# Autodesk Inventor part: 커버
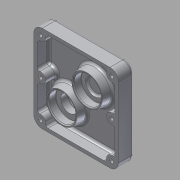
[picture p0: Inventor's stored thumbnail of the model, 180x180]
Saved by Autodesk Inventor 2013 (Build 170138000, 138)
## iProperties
Created: 2015-10
Part Number: 커버
Material: 알루미늄 6061
Document SubType Name: Modeling
Designer: mduedu
Density: 2.71 g/cm^3
Mass: 254.004 g
Surface Area: 401.286 cm^2
Volume: 93.7286 cm^3
Author: mduedu
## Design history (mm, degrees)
sketch "스케치1"
  geometry: L1 (-50, -51.5)-(50, -51.5); L2 (50, -51.5)-(50, 51.5); L3 (50, 51.5)-(-50, 51.5); L4 (-50, 51.5)-(-50, -51.5); L5 (-50, -51.5)-(50, 51.5); L6 (50, -51.5)-(-50, 51.5); 1 further point
  constraints: 12 end point, 2 midpoint, 2 parallel, 1 horizontal, 1 perpendicular
  dimensions: "d0" = 100 distance of L3.end L2.end; "d1" = 103 distance of L2.end L1.end
extrude "돌출1" new body sketch "스케치1" distance "d2" = 18; taper "d3" = 0 deg
fillet "모깎기1" dims "d4" = 10
fillet "모깎기2" dims "d5" = 3
feature "쉘1" dims "d6" = 4
sketch "스케치2"
  geometry: L1 (40, 51.5)-(-40, 51.5) reference; L2 (50, -41.5)-(50, 41.5) reference; L3 (-40, -51.5)-(40, -51.5) reference; L4 (-50, 41.5)-(-50, -41.5) reference; L5 (-50, 0)-(50, 0); L6 (0, 51.5)-(0, -51.5); C1 r 6 at (-42, 43.5); C2 r 6 at (-42, 0); C3 r 6 at (-42, -43.5); C4 r 6 at (42, -43.5); C5 r 6 at (42, 0); C6 r 6 at (42, 43.5); 1 further point
  constraints: 6 centre point, 4 end point, 4 midpoint, 4 symmetric about line, 1 equal radius, 1 point on line, 1 vertical alignment, 4 other
  dimensions: "d7" = 12 diameter of C1; "d8" = 8 distance from line of C1.centre L1; "d9" = 8 distance from line of C1.centre L4
extrude "돌출2" join sketch "스케치2" stored distance "d10" = 0; taper "d11" = 0 deg
fillet "모깎기3" dims "d12" = 3
fillet "모깎기4" dims "d13" = 3
sketch "스케치3"
  geometry: A1 r 6 centre (42, 43.5) between (36.037, 44.167) and (42.667, 37.537) reference; A2 r 6 centre (42, 0) between (42.667, 5.963) and (42.667, -5.963) reference; A3 r 6 centre (42, -43.5) between (42.667, -37.537) and (36.037, -44.167) reference; A4 r 6 centre (-42, -43.5) between (-36.037, -44.167) and (-42.667, -37.537) reference; A5 r 6 centre (-42, 0) between (-42.667, -5.963) and (-42.667, 5.963) reference; A6 r 6 centre (-42, 43.5) between (-42.667, 37.537) and (-36.037, 44.167) reference; 7 further points
  constraints: 6 coincident
hole "구멍1" sketch "스케치3" at (-42, 43.5), (-42, 0), (-42, -43.5), (42, -43.5), (42, 0), (42, 43.5) diameter "d14" = 4.5; stored, may be unused: countersink angle "d18" = 90 deg, drill point angle "d20" = 118 deg; dims "d15" = 6, "d16" = 8, "d17" = 4.4, "d19" = 8
sketch "스케치4"
  geometry: L1 (83.056, 3)-(83.056, 86) reference; L2 (73.056, 96)-(-6.944, 96) reference; C1 r 20 at (43.056, 56); 1 further point
  constraints: 1 centre point
  dimensions: "d21" = 40 diameter of C1; "d22" = 40 distance from line of C1.centre L1; "d23" = 40 distance from line of C1.centre L2
extrude "돌출3" join sketch "스케치4" distance "d24" = 11; taper "d25" = -10 deg
hole "구멍2" diameter "d28" = 22; stored, may be unused: countersink angle "d32" = 90 deg, drill point angle "d34" = 0 deg; dims "d29" = 6, "d30" = 32, "d31" = 9, "d33" = 11, "d35" = 10, "d36" = 10
sketch "스케치5"
  geometry: L1 (-40, -51.5)-(40, -51.5) reference; L2 (50, -41.5)-(50, 41.5) reference; C1 r 25 at (20, -21.5); 1 further point
  constraints: 1 centre point
  dimensions: "d37" = 50 diameter of C1; "d40" = 30 distance from line of C1.centre L1; "d41" = 30 distance from line of C1.centre L2
extrude "돌출4" join sketch "스케치5" distance "d42" = 15; taper "d43" = -10 deg
sketch "스케치6"
  geometry: C1 r 25 at (13.056, 23) reference; C2 r 20 at (13.056, 23); 1 further point
  constraints: 1 centre point, 1 coincident
  dimensions: "d44" = 40 diameter of C2
extrude "돌출5" join sketch "스케치6" distance "d45" = 11; taper "d46" = -10 deg
hole "구멍3" diameter "d49" = 20; stored, may be unused: countersink angle "d53" = 90 deg, drill point angle "d55" = 118 deg; dims "d47" = 10, "d48" = 10, "d50" = 6, "d51" = 32, "d52" = 9, "d54" = 11
hole "구멍4" diameter "d58" = 24; stored, may be unused: countersink angle "d62" = 90 deg, drill point angle "d64" = 0 deg; dims "d56" = 10, "d57" = 10, "d59" = 6, "d60" = 28, "d61" = 11, "d63" = 13
chamfer "모따기1" distance "d65" = 1; stored, may be unused: second distance "d66" = 2, angle "d67" = 45 deg
sketch "스케치7" dims "d68" = 36
  geometry: C1 r 25 at (0, 0) reference; 3 further points
  constraints: 2 vertical alignment, 1 coincident, 2 other
hole "구멍5" sketch "스케치7" at (0, 18) diameter "d69" = 2.459; stored, may be unused: countersink angle "d73" = 90 deg, drill point angle "d75" = 118 deg; dims "d70" = 8, "d71" = 28, "d72" = 11, "d74" = 10
sketch "스케치8"
  geometry: L1 (-50, 41.5)-(-50, -41.5) reference; L2 (40, 51.5)-(-40, 51.5) reference; 2 further points
  constraints: 1 other
  dimensions: "d79" = 50 distance from line of point (0, 26.5) L1; "d80" = 25 distance from line of point (0, 26.5) L2
feature "엠보싱1" sketch "스케치8" dims "d0" = 100, "d1" = 103, "d5" = 3, "d81" = 0.5, "d82" = 0
fillet "모깎기5" dims "d83" = 3
fillet "모깎기6" dims "d84" = 3
fillet "모깎기7" dims "d85" = 3
fillet "모깎기8" dims "d86" = 0.3
fillet "모깎기9" dims "d87" = 3
node "솔리드1"
pattern_circular "원형 패턴1" dims angle "d77" = 360 deg
